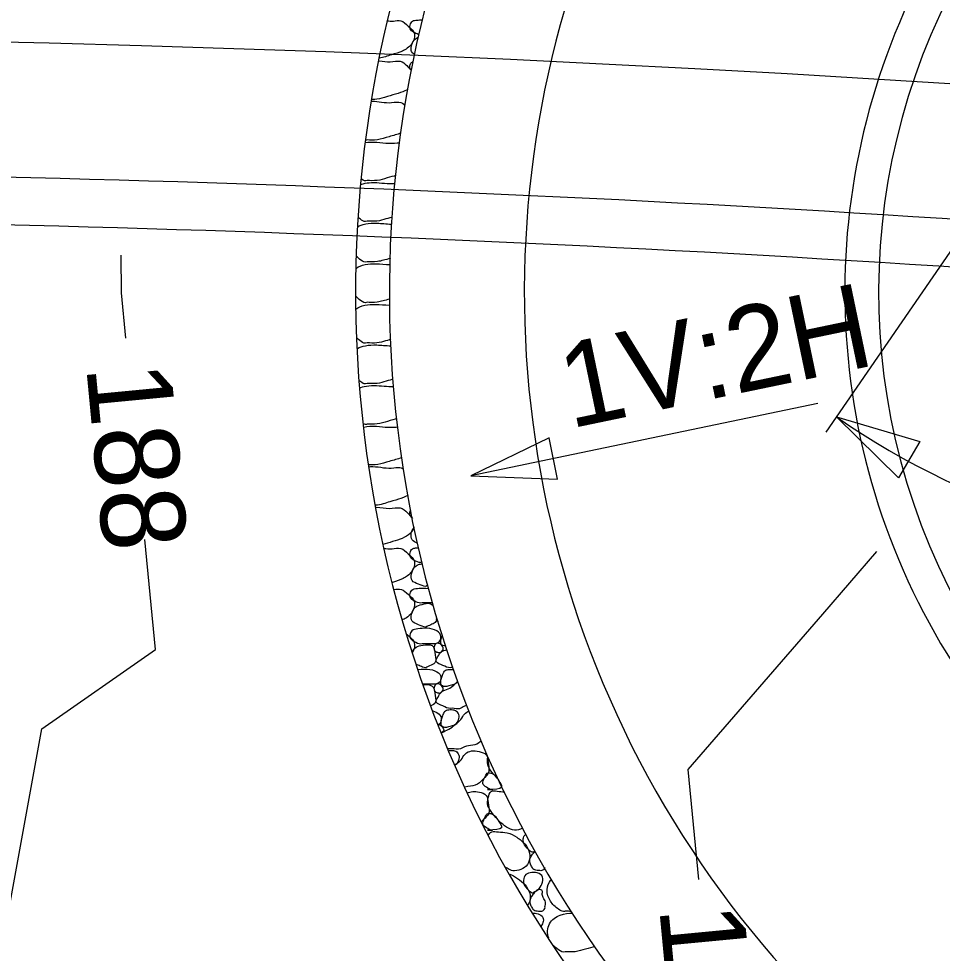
# Model space of a CAD drawing. Extents: x 1385284 to 1385995, y 1975154 to 1975620.
# Drawn here: x 1385530.9 to 1385558.27, y 1975451.37 to 1975479.07 of the extents above; entities that cross this region are included whole.
import ezdxf

# ---------------------------------------------------------------- set-up
doc = ezdxf.new("R2010")
doc.units = 0
for name, color, linetype in [('Default', 7, 'Continuous'), ('DTM_CONTOURS_MINOR', 7, 'Continuous'), ('R_Bridge', 7, 'Continuous'), ('R_Horz Alg', 7, 'Continuous'), ('R_Proposed Const Limits', 7, 'Continuous'), ('R_Proposed Road', 7, 'Continuous')]:
    doc.layers.add(name, color=color, linetype=linetype)

msp = doc.modelspace()

# ---------------------------------------------------------------- linework, layer by layer
at = {"layer": 'Default'}
for p, q in [((1385568.987, 1975487.408), (1385554.822, 1975466.808)), ((1385554.583, 1975467.663), (1385544.298, 1975465.522))]:
    msp.add_line(p, q, dxfattribs=at)
for points in [[(1385556.977, 1975465.461), (1385555.134, 1975467.262), (1385557.608, 1975466.54)], [(1385546.618, 1975466.643), (1385544.298, 1975465.522), (1385546.873, 1975465.419)]]:
    msp.add_lwpolyline(points, close=True, dxfattribs=at)
for centre, radius, start, end in [((1385575.884, 1975470.965), 35, 144.0867, 263.6071), ((1385575.884, 1975470.965), 34, 144.0867, 263.6071), ((1385575.884, 1975470.965), 20.5, 145.4884, 267.767), ((1385575.884, 1975470.965), 19.5, 145.3879, 267.767), ((1385568.987, 1975487.408), 24.449, 235.4884, 270)]:
    msp.add_arc(centre, radius, start, end, dxfattribs=at)
for points in [[(1385541.831, 1975479), (1385541.872, 1975478.997), (1385541.996, 1975478.98), (1385542.234, 1975479.05), (1385542.437, 1975478.844), (1385542.69, 1975478.641), (1385542.564, 1975478.28), (1385542.275, 1975478.09), (1385541.955, 1975477.999), (1385541.701, 1975477.915), (1385541.593, 1975477.894)], [(1385542.766, 1975478.592), (1385542.734, 1975478.6), (1385542.633, 1975478.644), (1385542.496, 1975478.715), (1385542.485, 1975478.881), (1385542.562, 1975479.013), (1385542.701, 1975479.022), (1385542.799, 1975479.03), (1385542.86, 1975479.031)], [(1385542.638, 1975477.999), (1385542.614, 1975478.013), (1385542.522, 1975478.073), (1385542.526, 1975478.253), (1385542.605, 1975478.442), (1385542.712, 1975478.504), (1385542.75, 1975478.52)], [(1385541.576, 1975477.815), (1385541.702, 1975477.807), (1385541.911, 1975477.762), (1385542.234, 1975477.847), (1385542.4, 1975477.67), (1385542.503, 1975477.567), (1385542.536, 1975477.526)], [(1385542.536, 1975477.525), (1385542.529, 1975477.533), (1385542.488, 1975477.577), (1385542.485, 1975477.678), (1385542.535, 1975477.775), (1385542.586, 1975477.799), (1385542.595, 1975477.802)], [(1385542.419, 1975476.96), (1385542.398, 1975476.945), (1385542.232, 1975476.872), (1385541.907, 1975476.787), (1385541.581, 1975476.672), (1385541.393, 1975476.67), (1385541.366, 1975476.67)], [(1385541.359, 1975476.62), (1385541.388, 1975476.621), (1385541.587, 1975476.615), (1385541.868, 1975476.551), (1385542.195, 1975476.628), (1385542.308, 1975476.545), (1385542.352, 1975476.505)], [(1385541.177, 1975475.395), (1385541.267, 1975475.413), (1385541.526, 1975475.418), (1385541.861, 1975475.351), (1385542.109, 1975475.392), (1385542.186, 1975475.385)], [(1385541.23, 1975475.472), (1385541.217, 1975475.466), (1385541.202, 1975475.463), (1385541.187, 1975475.462)], [(1385542.229, 1975475.673), (1385542.126, 1975475.635), (1385541.865, 1975475.569), (1385541.536, 1975475.455), (1385541.302, 1975475.469), (1385541.23, 1975475.472)], [(1385541.23, 1975474.269), (1385541.181, 1975474.245), (1385541.118, 1975474.269), (1385541.059, 1975474.305)], [(1385542.071, 1975474.416), (1385542.02, 1975474.4), (1385541.812, 1975474.347), (1385541.536, 1975474.252), (1385541.302, 1975474.266), (1385541.23, 1975474.269)], [(1385541.047, 1975474.155), (1385541.072, 1975474.165), (1385541.206, 1975474.204), (1385541.508, 1975474.217), (1385541.817, 1975474.172), (1385542.019, 1975474.18), (1385542.052, 1975474.181)], [(1385540.944, 1975472.9), (1385541, 1975472.935), (1385541.168, 1975472.996), (1385541.508, 1975473.014), (1385541.785, 1975472.986), (1385541.954, 1975472.977)], [(1385541.23, 1975473.066), (1385541.162, 1975473.032), (1385541.054, 1975473.099), (1385540.975, 1975473.164), (1385540.967, 1975473.171)], [(1385541.97, 1975473.183), (1385541.952, 1975473.178), (1385541.778, 1975473.132), (1385541.536, 1975473.049), (1385541.302, 1975473.063), (1385541.23, 1975473.066)], [(1385541.23, 1975471.863), (1385541.162, 1975471.829), (1385541.03, 1975471.911), (1385540.939, 1975471.992), (1385540.915, 1975472.016)], [(1385541.914, 1975471.964), (1385541.759, 1975471.922), (1385541.535, 1975471.846), (1385541.302, 1975471.86), (1385541.23, 1975471.863)], [(1385540.91, 1975471.674), (1385540.975, 1975471.72), (1385541.154, 1975471.792), (1385541.494, 1975471.812), (1385541.757, 1975471.786), (1385541.911, 1975471.777)], [(1385541.23, 1975470.661), (1385541.162, 1975470.626), (1385541.02, 1975470.714), (1385540.925, 1975470.802), (1385540.897, 1975470.833)], [(1385541.895, 1975470.756), (1385541.747, 1975470.715), (1385541.528, 1975470.643), (1385541.302, 1975470.657), (1385541.23, 1975470.661)], [(1385540.891, 1975470.457), (1385540.96, 1975470.51), (1385541.147, 1975470.588), (1385541.488, 1975470.609), (1385541.744, 1975470.584), (1385541.892, 1975470.575)], [(1385541.23, 1975469.458), (1385541.162, 1975469.423), (1385541.036, 1975469.501), (1385540.948, 1975469.578), (1385540.928, 1975469.598)], [(1385540.943, 1975469.29), (1385540.999, 1975469.326), (1385541.168, 1975469.387), (1385541.504, 1975469.405), (1385541.776, 1975469.378), (1385541.94, 1975469.369)], [(1385541.93, 1975469.563), (1385541.926, 1975469.561), (1385541.765, 1975469.518), (1385541.536, 1975469.44), (1385541.302, 1975469.454), (1385541.23, 1975469.458)], [(1385541.23, 1975468.255), (1385541.162, 1975468.22), (1385541.064, 1975468.28), (1385540.992, 1975468.338), (1385540.991, 1975468.339)], [(1385541.99, 1975468.376), (1385541.966, 1975468.369), (1385541.785, 1975468.322), (1385541.536, 1975468.237), (1385541.302, 1975468.252), (1385541.23, 1975468.255)], [(1385541.002, 1975468.12), (1385541.041, 1975468.14), (1385541.19, 1975468.187), (1385541.508, 1975468.202), (1385541.8, 1975468.166), (1385541.985, 1975468.164), (1385542.001, 1975468.165)], [(1385542.11, 1975467.211), (1385542.046, 1975467.19), (1385541.825, 1975467.134), (1385541.536, 1975467.034), (1385541.302, 1975467.049), (1385541.23, 1975467.052)], [(1385541.23, 1975467.052), (1385541.199, 1975467.036), (1385541.161, 1975467.04), (1385541.122, 1975467.055)], [(1385541.133, 1975466.964), (1385541.238, 1975466.989), (1385541.511, 1975466.999), (1385541.846, 1975466.939), (1385542.077, 1975466.967), (1385542.139, 1975466.966)], [(1385542.246, 1975466.055), (1385542.137, 1975466.015), (1385541.871, 1975465.947), (1385541.547, 1975465.834), (1385541.325, 1975465.844), (1385541.264, 1975465.847)], [(1385541.271, 1975465.786), (1385541.33, 1975465.793), (1385541.557, 1975465.791), (1385541.868, 1975465.724), (1385542.165, 1975465.788), (1385542.268, 1975465.741), (1385542.296, 1975465.723)], [(1385542.44, 1975464.945), (1385542.413, 1975464.924), (1385542.24, 1975464.845), (1385541.917, 1975464.759), (1385541.628, 1975464.658), (1385541.479, 1975464.644)], [(1385541.49, 1975464.588), (1385541.644, 1975464.58), (1385541.882, 1975464.524), (1385542.234, 1975464.614), (1385542.416, 1975464.424), (1385542.53, 1975464.307), (1385542.568, 1975464.25)], [(1385542.566, 1975464.261), (1385542.549, 1975464.277), (1385542.49, 1975464.328), (1385542.483, 1975464.426), (1385542.508, 1975464.489), (1385542.521, 1975464.509)], [(1385542.614, 1975464.002), (1385542.598, 1975463.939), (1385542.517, 1975463.803), (1385542.275, 1975463.654), (1385541.99, 1975463.57), (1385541.768, 1975463.501), (1385541.694, 1975463.482)], [(1385542.713, 1975463.526), (1385542.661, 1975463.549), (1385542.523, 1975463.604), (1385542.525, 1975463.808), (1385542.567, 1975463.929), (1385542.617, 1975463.988)], [(1385541.721, 1975463.369), (1385541.799, 1975463.363), (1385541.959, 1975463.335), (1385542.234, 1975463.411), (1385542.437, 1975463.206), (1385542.69, 1975463.002), (1385542.564, 1975462.641), (1385542.296, 1975462.46), (1385542.105, 1975462.395), (1385541.979, 1975462.358)], [(1385542.858, 1975462.956), (1385542.802, 1975462.932), (1385542.657, 1975462.99), (1385542.496, 1975463.076), (1385542.485, 1975463.243), (1385542.562, 1975463.374), (1385542.664, 1975463.379), (1385542.725, 1975463.384), (1385542.748, 1975463.386)], [(1385542.858, 1975462.956), (1385542.858, 1975462.956), (1385542.858, 1975462.956), (1385542.858, 1975462.956)], [(1385542.963, 1975462.236), (1385542.891, 1975462.246), (1385542.746, 1975462.315), (1385542.523, 1975462.386), (1385542.526, 1975462.614), (1385542.636, 1975462.86), (1385542.785, 1975462.895), (1385542.865, 1975462.92), (1385542.867, 1975462.92)], [(1385542.032, 1975462.151), (1385542.089, 1975462.153), (1385542.252, 1975462.187), (1385542.437, 1975462.003), (1385542.69, 1975461.799), (1385542.564, 1975461.438), (1385542.39, 1975461.299), (1385542.291, 1975461.26), (1385542.261, 1975461.249)], [(1385542.858, 1975461.753), (1385542.802, 1975461.729), (1385542.657, 1975461.787), (1385542.496, 1975461.873), (1385542.485, 1975462.04), (1385542.562, 1975462.171), (1385542.765, 1975462.188), (1385542.929, 1975462.197), (1385543.055, 1975462.183)], [(1385543.033, 1975462.27), (1385543.009, 1975462.259), (1385542.986, 1975462.248), (1385542.963, 1975462.236)], [(1385542.963, 1975461.033), (1385542.891, 1975461.043), (1385542.746, 1975461.112), (1385542.523, 1975461.183), (1385542.526, 1975461.411), (1385542.636, 1975461.657), (1385542.852, 1975461.706), (1385543.099, 1975461.772), (1385543.177, 1975461.676), (1385543.189, 1975461.656)], [(1385543.165, 1975461.752), (1385543.062, 1975461.75), (1385542.96, 1975461.748), (1385542.858, 1975461.753)], [(1385543.296, 1975461.29), (1385543.298, 1975461.254), (1385543.248, 1975461.163), (1385543.114, 1975461.105), (1385543.011, 1975461.057), (1385542.963, 1975461.033)], [(1385543.328, 1975461.19), (1385543.311, 1975461.207), (1385543.278, 1975461.238), (1385543.286, 1975461.28), (1385543.293, 1975461.298)], [(1385542.858, 1975460.55), (1385542.802, 1975460.526), (1385542.657, 1975460.584), (1385542.496, 1975460.67), (1385542.485, 1975460.837), (1385542.562, 1975460.968), (1385542.781, 1975460.987), (1385543.081, 1975461.017), (1385543.38, 1975460.894), (1385543.439, 1975460.708), (1385543.343, 1975460.542), (1385543.138, 1975460.549), (1385542.977, 1975460.544), (1385542.858, 1975460.55)], [(1385542.396, 1975460.825), (1385542.405, 1975460.817), (1385542.49, 1975460.742), (1385542.663, 1975460.61), (1385542.625, 1975460.384), (1385542.572, 1975460.287)], [(1385543.56, 1975460.483), (1385543.553, 1975460.481), (1385543.509, 1975460.469), (1385543.424, 1975460.5), (1385543.397, 1975460.606), (1385543.424, 1975460.707), (1385543.447, 1975460.779), (1385543.455, 1975460.803)], [(1385542.567, 1975460.303), (1385542.584, 1975460.338), (1385542.673, 1975460.463), (1385542.852, 1975460.503), (1385543.213, 1975460.533), (1385543.216, 1975460.291), (1385543.298, 1975459.98), (1385543.114, 1975459.902), (1385543.011, 1975459.854), (1385542.963, 1975459.83)], [(1385543.401, 1975460.284), (1385543.364, 1975460.284), (1385543.279, 1975460.282), (1385543.2, 1975460.363), (1385543.208, 1975460.481), (1385543.292, 1975460.584), (1385543.419, 1975460.533), (1385543.523, 1975460.373), (1385543.435, 1975460.313), (1385543.401, 1975460.284)], [(1385543.686, 1975459.83), (1385543.615, 1975459.825), (1385543.479, 1975459.905), (1385543.219, 1975459.994), (1385543.333, 1975460.163), (1385543.401, 1975460.327), (1385543.531, 1975460.346), (1385543.596, 1975460.374)], [(1385542.963, 1975459.83), (1385542.891, 1975459.84), (1385542.797, 1975459.882), (1385542.709, 1975459.918), (1385542.69, 1975459.927)], [(1385542.739, 1975459.777), (1385542.861, 1975459.787), (1385543.098, 1975459.805), (1385543.38, 1975459.691), (1385543.439, 1975459.505), (1385543.343, 1975459.339), (1385543.145, 1975459.346), (1385542.993, 1975459.341), (1385542.88, 1975459.346)], [(1385543.829, 1975459.347), (1385543.782, 1975459.332), (1385543.685, 1975459.309), (1385543.551, 1975459.255), (1385543.424, 1975459.297), (1385543.397, 1975459.403), (1385543.427, 1975459.517), (1385543.471, 1975459.644), (1385543.531, 1975459.769), (1385543.658, 1975459.782), (1385543.745, 1975459.782), (1385543.793, 1975459.771)], [(1385543.772, 1975459.833), (1385543.743, 1975459.836), (1385543.714, 1975459.837), (1385543.686, 1975459.83)], [(1385542.889, 1975459.318), (1385542.972, 1975459.344), (1385543.214, 1975459.32), (1385543.216, 1975459.088), (1385543.299, 1975458.778), (1385543.165, 1975458.726), (1385543.113, 1975458.7)], [(1385543.401, 1975459.081), (1385543.364, 1975459.081), (1385543.279, 1975459.079), (1385543.2, 1975459.16), (1385543.208, 1975459.278), (1385543.292, 1975459.381), (1385543.419, 1975459.33), (1385543.523, 1975459.17), (1385543.435, 1975459.11), (1385543.401, 1975459.081)], [(1385543.686, 1975458.627), (1385543.615, 1975458.622), (1385543.479, 1975458.702), (1385543.219, 1975458.791), (1385543.333, 1975458.96), (1385543.413, 1975459.147), (1385543.637, 1975459.191), (1385543.8, 1975459.318), (1385543.881, 1975459.397), (1385543.907, 1975459.422)], [(1385543.905, 1975459.427), (1385543.886, 1975459.395), (1385543.861, 1975459.365), (1385543.829, 1975459.347)], [(1385543.172, 1975458.553), (1385543.24, 1975458.532), (1385543.387, 1975458.462), (1385543.439, 1975458.302), (1385543.383, 1975458.156), (1385543.336, 1975458.148), (1385543.335, 1975458.147)], [(1385543.829, 1975458.144), (1385543.782, 1975458.129), (1385543.685, 1975458.106), (1385543.551, 1975458.052), (1385543.424, 1975458.094), (1385543.397, 1975458.2), (1385543.427, 1975458.314), (1385543.471, 1975458.441), (1385543.531, 1975458.566), (1385543.682, 1975458.582), (1385543.854, 1975458.578), (1385543.966, 1975458.451), (1385543.942, 1975458.291), (1385543.882, 1975458.174), (1385543.829, 1975458.144)], [(1385543.434, 1975457.903), (1385543.501, 1975457.944), (1385543.648, 1975457.997), (1385543.838, 1975458.147), (1385544.017, 1975458.289), (1385544.102, 1975458.477), (1385544.203, 1975458.529), (1385544.252, 1975458.546)], [(1385544.185, 1975458.714), (1385544.162, 1975458.71), (1385544.078, 1975458.692), (1385543.931, 1975458.568), (1385543.765, 1975458.647), (1385543.686, 1975458.627)], [(1385543.334, 1975458.151), (1385543.367, 1975458.149), (1385543.439, 1975458.107), (1385543.529, 1975457.977), (1385543.458, 1975457.924), (1385543.433, 1975457.904)], [(1385543.686, 1975457.424), (1385543.666, 1975457.423), (1385543.645, 1975457.425), (1385543.625, 1975457.429)], [(1385544.608, 1975457.664), (1385544.569, 1975457.624), (1385544.421, 1975457.51), (1385544.168, 1975457.54), (1385543.931, 1975457.365), (1385543.765, 1975457.444), (1385543.686, 1975457.424)], [(1385543.647, 1975457.372), (1385543.648, 1975457.372), (1385543.72, 1975457.378), (1385543.854, 1975457.375), (1385543.966, 1975457.248), (1385543.942, 1975457.088), (1385543.882, 1975456.971), (1385543.829, 1975456.941)], [(1385543.823, 1975456.936), (1385543.825, 1975456.938), (1385543.89, 1975456.997), (1385544.017, 1975457.086), (1385544.112, 1975457.292), (1385544.323, 1975457.385), (1385544.538, 1975457.359), (1385544.802, 1975457.273), (1385544.794, 1975457.045), (1385544.88, 1975456.734), (1385544.666, 1975456.527), (1385544.446, 1975456.306), (1385544.237, 1975456.327), (1385544.123, 1975456.294)], [(1385545.13, 1975456.507), (1385545.065, 1975456.575), (1385544.927, 1975456.722), (1385544.778, 1975456.947), (1385544.792, 1975457.121), (1385544.803, 1975457.186)], [(1385543.829, 1975456.941), (1385543.826, 1975456.94), (1385543.824, 1975456.94), (1385543.822, 1975456.939)], [(1385544.912, 1975456.221), (1385544.865, 1975456.22), (1385544.769, 1975456.293), (1385544.606, 1975456.386), (1385544.715, 1975456.571), (1385544.763, 1975456.736), (1385544.944, 1975456.71), (1385545.064, 1975456.605), (1385545.131, 1975456.461), (1385545.318, 1975456.212), (1385544.568, 1975456.229), (1385544.954, 1975456.219), (1385544.946, 1975456.221)], [(1385544.206, 1975456.122), (1385544.237, 1975456.136), (1385544.36, 1975456.18), (1385544.538, 1975456.156), (1385544.802, 1975456.07), (1385544.794, 1975455.842), (1385544.88, 1975455.531), (1385544.715, 1975455.373), (1385544.63, 1975455.281), (1385544.618, 1975455.269)], [(1385545.595, 1975455.018), (1385545.524, 1975455.015), (1385545.341, 1975455.099), (1385545.144, 1975455.281), (1385544.934, 1975455.505), (1385544.776, 1975455.745), (1385544.808, 1975455.971), (1385544.879, 1975456.213), (1385545.082, 1975456.163), (1385545.222, 1975456.158), (1385545.303, 1975456.148)], [(1385544.912, 1975455.018), (1385544.865, 1975455.017), (1385544.769, 1975455.09), (1385544.606, 1975455.183), (1385544.715, 1975455.368), (1385544.763, 1975455.533), (1385544.944, 1975455.507), (1385545.064, 1975455.402), (1385545.131, 1975455.258), (1385545.318, 1975455.009), (1385544.568, 1975455.026), (1385544.954, 1975455.016), (1385544.946, 1975455.018)], [(1385544.817, 1975454.857), (1385544.827, 1975454.896), (1385544.902, 1975455.002), (1385545.108, 1975454.958), (1385545.378, 1975454.963), (1385545.667, 1975454.818), (1385545.924, 1975454.607), (1385546.072, 1975454.348), (1385546.034, 1975454.031), (1385545.848, 1975453.859), (1385545.68, 1975453.814), (1385545.595, 1975453.815)], [(1385545.828, 1975455.077), (1385545.751, 1975455.036), (1385545.672, 1975455.017), (1385545.595, 1975455.018)], [(1385546.172, 1975454.389), (1385546.141, 1975454.315), (1385545.937, 1975454.496), (1385545.835, 1975454.675), (1385545.86, 1975454.84), (1385545.913, 1975454.889), (1385545.929, 1975454.9)], [(1385546.494, 1975453.906), (1385546.487, 1975453.886), (1385546.435, 1975453.806), (1385546.318, 1975453.82), (1385546.139, 1975453.839), (1385546.102, 1975453.955), (1385546.027, 1975454.064), (1385546.066, 1975454.228), (1385546.149, 1975454.328), (1385546.199, 1975454.385), (1385546.213, 1975454.399)], [(1385546.21, 1975454.406), (1385546.198, 1975454.4), (1385546.186, 1975454.394), (1385546.172, 1975454.389)], [(1385545.595, 1975453.815), (1385545.524, 1975453.812), (1385545.434, 1975453.851), (1385545.353, 1975453.904), (1385545.34, 1975453.913)], [(1385545.456, 1975453.709), (1385545.517, 1975453.688), (1385545.685, 1975453.6), (1385545.924, 1975453.404), (1385546.072, 1975453.145), (1385546.055, 1975452.894), (1385545.998, 1975452.81), (1385545.979, 1975452.788)], [(1385546.172, 1975453.186), (1385546.141, 1975453.112), (1385545.937, 1975453.293), (1385545.835, 1975453.472), (1385545.885, 1975453.692), (1385546.049, 1975453.765), (1385546.276, 1975453.772), (1385546.466, 1975453.647), (1385546.415, 1975453.409), (1385546.302, 1975453.244), (1385546.198, 1975453.196), (1385546.172, 1975453.186)], [(1385547.099, 1975452.616), (1385547.032, 1975452.582), (1385546.808, 1975452.719), (1385546.593, 1975452.964), (1385546.523, 1975453.358), (1385546.659, 1975453.522), (1385546.692, 1975453.555)], [(1385546.499, 1975452.717), (1385546.488, 1975452.692), (1385546.44, 1975452.602), (1385546.318, 1975452.617), (1385546.139, 1975452.636), (1385546.102, 1975452.752), (1385546.027, 1975452.861), (1385546.066, 1975453.025), (1385546.161, 1975453.137), (1385546.238, 1975453.225), (1385546.318, 1975453.281), (1385546.442, 1975453.23), (1385546.399, 1975453.113), (1385546.461, 1975452.987), (1385546.544, 1975452.851), (1385546.48, 1975452.747), (1385546.499, 1975452.717)], [(1385546.12, 1975452.56), (1385546.173, 1975452.566), (1385546.299, 1975452.551), (1385546.466, 1975452.444), (1385546.443, 1975452.265), (1385546.397, 1975452.189), (1385546.38, 1975452.164)], [(1385546.611, 1975451.814), (1385546.547, 1975451.949), (1385546.578, 1975452.29), (1385546.941, 1975452.535), (1385547.209, 1975452.565), (1385547.316, 1975452.56)], [(1385547.283, 1975452.611), (1385547.222, 1975452.61), (1385547.16, 1975452.613), (1385547.099, 1975452.616)], [(1385547.099, 1975451.413), (1385547.032, 1975451.379), (1385546.882, 1975451.471), (1385546.784, 1975451.564), (1385546.752, 1975451.601)], [(1385547.97, 1975451.569), (1385547.909, 1975451.549), (1385547.691, 1975451.494), (1385547.405, 1975451.395), (1385547.172, 1975451.41), (1385547.099, 1975451.413)]]:
    msp.add_open_spline(points, degree=3, dxfattribs=at)
at = {"layer": 'DTM_CONTOURS_MINOR'}
for points in [[(1385534.071, 1975469.601), (1385533.944, 1975470.936), (1385533.934, 1975472.055)], [(1385457.074, 1975380.205), (1385470.036, 1975391.55), (1385472.648, 1975393.763), (1385483.141, 1975404.025), (1385486.704, 1975407.042), (1385496.298, 1975416.333), (1385500.663, 1975420.022), (1385509.505, 1975428.49), (1385514.554, 1975432.762), (1385520.463, 1975437.019), (1385529.241, 1975445.201), (1385531.584, 1975458.02), (1385534.953, 1975460.368), (1385534.641, 1975463.628)], [(1385551.055, 1975453.558), (1385550.745, 1975456.813), (1385554.731, 1975461.421), (1385556.333, 1975463.273)]]:
    msp.add_lwpolyline(points, dxfattribs=at)
at = {"layer": 'R_Bridge'}
for radius in [679.494, 678.078]:
    msp.add_arc((1385514.357, 1974795.066), radius, 86.221345, 95.633125, dxfattribs=at)
at = {"layer": 'R_Horz Alg'}
msp.add_arc((1385514.357, 1974795.066), 694.494, 77.498258, 106.635112, dxfattribs=at)
at = {"layer": 'R_Proposed Const Limits'}
msp.add_arc((1385575.884, 1975470.965), 30, 145.4884, 267.767, dxfattribs=at)
at = {"layer": 'R_Proposed Road'}
for radius, end in [(705.494, 106.368381), (683.494, 106.910819)]:
    msp.add_arc((1385514.357, 1974795.066), radius, 77.498258, end, dxfattribs=at)

# ---------------------------------------------------------------- texts
at = {"layer": 'Default'}
for s, rotation, p in [('1V:2H', 11.7615, (1385547.239, 1975466.915)), ('188', 275.4519, (1385532.896, 1975468.761)), ('189', 275.4519, (1385549.88, 1975452.718))]:
    msp.add_text(s, height=2.5, rotation=rotation, dxfattribs=at).set_placement(p)

doc.saveas('drawing.dxf')
